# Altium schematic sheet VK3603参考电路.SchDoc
size A4
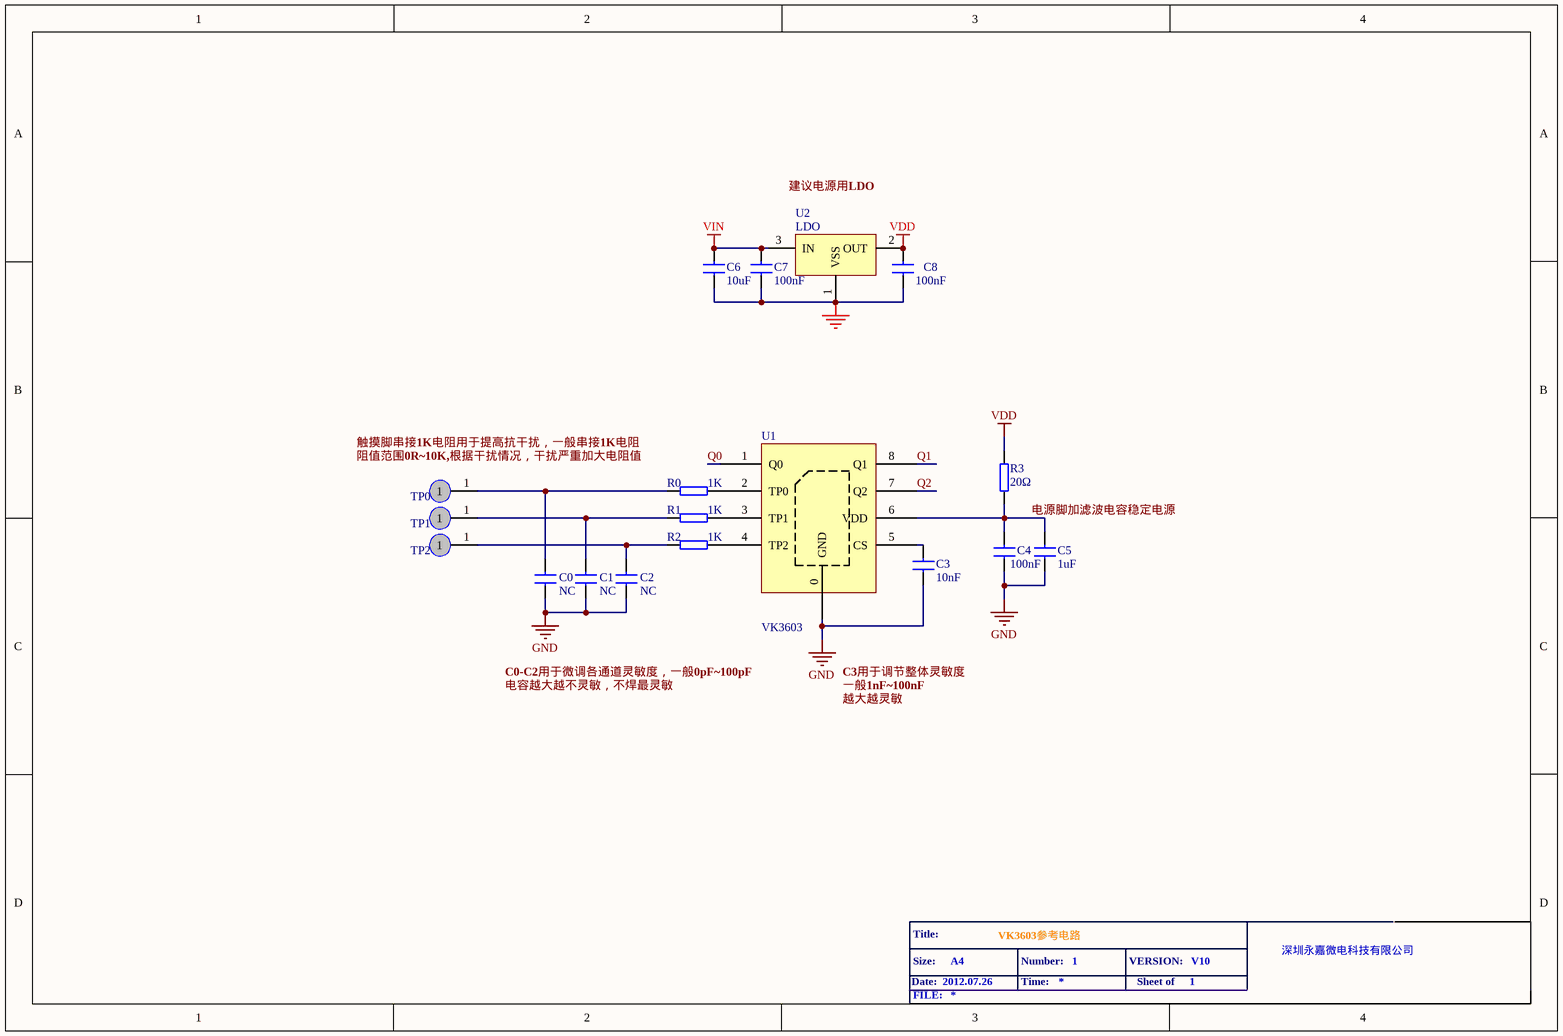
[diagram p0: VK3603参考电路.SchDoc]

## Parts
C0  value NC  [0603-C]  (hidden comment: 10uF)
C1  value NC  [0603-C]  (hidden comment: 10uF)
C2  value NC  [0603-C]  (hidden comment: 10uF)
C3  value 10nF  [0603-C]  (hidden comment: 10uF)
C4  100nF  [0603-C]
C5  value 1uF  [0603-C]  (hidden comment: 10uF)
C6  10uF  [0805-C]
C7  100nF  [0805-C]
C8  100nF  [0805-C]
R0  1K  [0603-R]
R1  1K  [0603-R]
R2  1K  [0603-R]
R3  20Ω  [0603-R]
TP0  TPAD  [TP-PAD0]  (value not drawn)
TP1  TPAD  [TP-PAD0]  (value not drawn)
TP2  TPAD  [TP-PAD0]  (value not drawn)
U1  VK3603
U2  LDO  [SOT-23]

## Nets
GND: C0.1 C1.1 C2.1 C3.2 C4.2 C5.2 C6.2 C7.2 C8.2 U1.0(GND) U2.1(VSS)
VDD: C8.1 R3.1 U2.2(OUT)
VIN: C6.1 C7.1 U2.3(IN)
Q0: U1.1(Q0)
Q1: U1.8(Q1)
Q2: U1.7(Q2)
NetC0_2: C0.2 R0.2 TP0.1
NetC1_2: C1.2 R1.2 TP1.1
NetC2_2: C2.2 R2.2 TP2.1
NetC3_1: C3.1 U1.5(CS)
NetC4_1: C4.1 C5.1 R3.2 U1.6(VDD)
NetR0_1: R0.1 U1.2(TP0)
NetR1_1: R1.1 U1.3(TP1)
NetR2_1: R2.1 U1.4(TP2)

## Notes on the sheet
- 建议电源用LDO
- (near TP0) 触摸脚串接1K电阻用于提高抗干扰，一般串接1K电阻
- (near TP0) 阻值范围0R
  0K,根据干扰情况，干扰严重加大电阻值
- 电源脚加滤波电容稳定电源
- C0-C2用于微调各通道灵敏度，一般0pF
  00pF
- 电容越大越不灵敏，不焊最灵敏
- C3用于调节整体灵敏度
- 一般1nF
  00nF
- 越大越灵敏
- Date:
- Title:
- Size:
- 2012.07.26
- A4
- VK3603参考电路
- Number:
- Time:
- 1
- VERSION:
- Sheet of
- V10
- 深圳永嘉微电科技有限公司
- FILE:

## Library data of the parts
C0-C8 = CAP: Capacitor
R0-R3 = RES: Resistor
TP0-TP2 = TPAD: TESTING
U1 = VK3603 SOP8-EP
U2 = V6206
